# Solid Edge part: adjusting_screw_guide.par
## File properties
Title: Adjusting screw guide
Author: Deepak Maini
Template: Normal.par
Last saved by: CADCIM
Revision: 3
Application: Solid Edge
Accuracy: 0.99
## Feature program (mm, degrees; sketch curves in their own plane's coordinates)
sketch for "unnamed Protrusion 1" plane through (0, 0, 0) normal (0, -1, 0) x-axis (1, 0, 0)
  circle centre (0, 0) radius 7.9375
extrude "unnamed Protrusion 1" add finite 63.5 along +normal
sketch for "ExtrudedProtrusion_2" plane through (0, -63.5, 0) normal (0, -1, 0) x-axis (1, 0, 0)
  circle centre (0, 0) radius 6.3119
extrude "ExtrudedProtrusion_2" add finite 76.2 along +normal
chamfer "Chamfer_1" setback 1.5748
sketch for "ExtrudedCutout_1" plane through (0, 0, 0) normal (0, 0, 1) x-axis (1, 0, 0)
  line (1.1811, 0) -> (1.1811, -4.7498)
  line (1.1811, -4.7498) -> (-1.1811, -4.7498)
  line (-1.1811, -4.7498) -> (-1.1811, 0)
  line (-1.1811, 0) -> (1.1811, 0)
extrude "ExtrudedCutout_1" cut finite 101.6 symmetric
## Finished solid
Body 1: solid body, 10 faces, 16 edges, 8 vertices.
  Faces by surface: plane 7, cylinder 2, cone 1
  Edges by curve: circle 8, line 8
Bounding box of the edges (mm): 15.875 x 139.700 x 15.875, from (-7.9375, -139.7, -7.9375) to (7.9375, 0, 7.9375).
Cylindrical faces by radius (mm): R6.3119 x1, R7.9375 x1
Conical faces (half-angle, radius in mm at the cone's reference point): 45 deg R6.3119 x1
Planar faces by outward normal: +x 1, +y 3, -x 1, -y 2
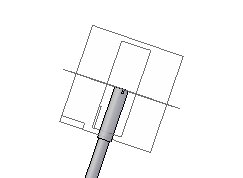
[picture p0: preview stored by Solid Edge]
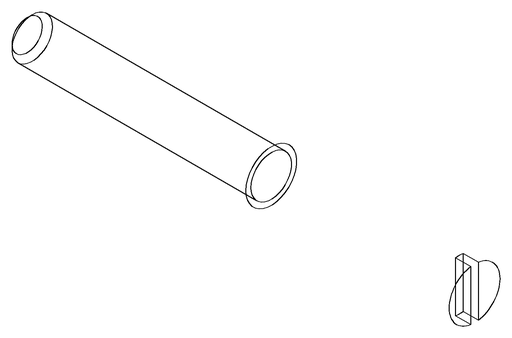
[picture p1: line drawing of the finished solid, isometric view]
